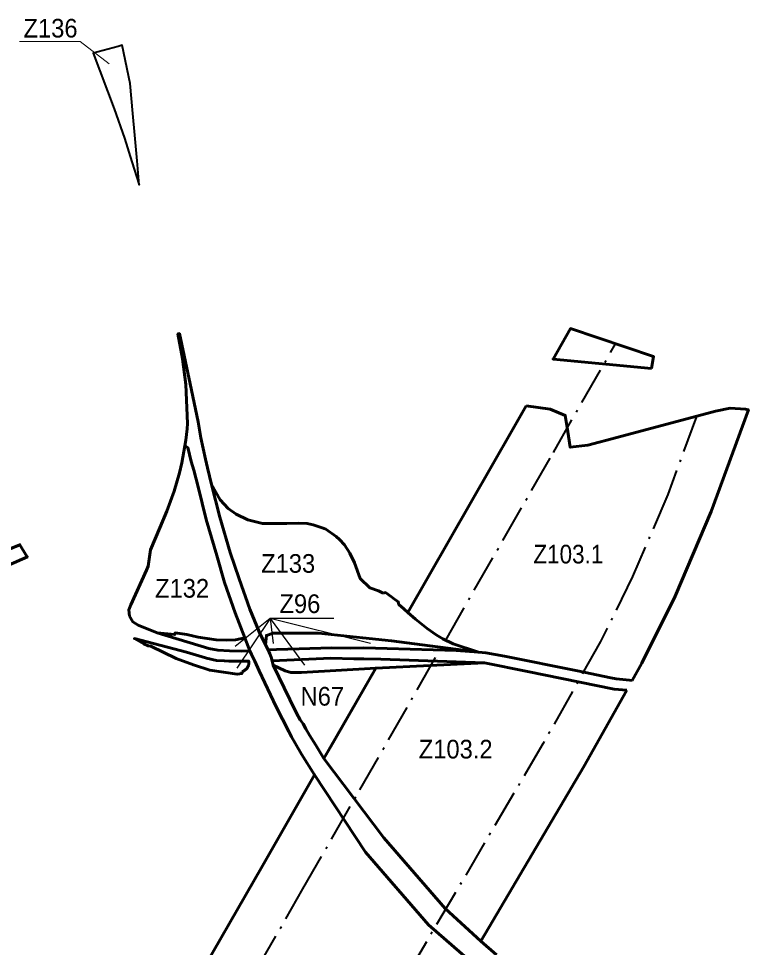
# Model space of a CAD drawing. Extents: x -650277 to -643425, y -1073980 to -1066720.
# Drawn here: x -647999 to -647061, y -1068122 to -1066928 of the extents above; entities that cross this region are included whole.
import ezdxf

# ---------------------------------------------------------------- set-up
doc = ezdxf.new("R2010")
doc.units = 0
doc.header["$LTSCALE"] = 9.6
doc.linetypes.add('DOT_DASHED', pattern=[7.7, 5, -1.2, 0.3, -1.2])
for name, color, linetype, lineweight in [('1', 7, 'Continuous', 60), ('15', 7, 'Continuous', 60), ('2', 7, 'Continuous', 40), ('42', 7, 'Continuous', 60), ('59', 7, 'Continuous', 25), ('60', 7, 'Continuous', 60), ('61', 7, 'Continuous', 60), ('62', 7, 'DOT_DASHED', 40), ('63', 7, 'Continuous', 25)]:
    doc.layers.add(name, color=color, linetype=linetype, lineweight=lineweight)

msp = doc.modelspace()

# ---------------------------------------------------------------- linework, layer by layer
at = {"layer": '1'}
for points in [[(-647708.71, -1067723.99), (-647721.05, -1067691.73), (-647734.63, -1067652.57), (-647744.61, -1067617.96), (-647758.25, -1067571.79), (-647768.5, -1067529.75), (-647773.96, -1067508.48), (-647777.55, -1067496.95), (-647781.85, -1067479.19), (-647785.64, -1067477.02), (-647789.39, -1067498.84), (-647792.54, -1067511.85), (-647799.39, -1067535.48)], [(-647704.458, -1067572.034), (-647719.661, -1067564.884), (-647729.802, -1067557.462), (-647740.124, -1067546.265), (-647751.41, -1067526.58), (-647740.49, -1067568.67), (-647727.37, -1067614.33), (-647715.92, -1067648.12), (-647702.04, -1067686.86), (-647690.09, -1067716.05), (-647681.91, -1067732.74), (-647680.804, -1067720.745), (-647672, -1067718), (-647643, -1067718), (-647614, -1067718), (-647557, -1067724), (-647520.145, -1067727.879), (-647408.2, -1067742.37)], [(-647799.39, -1067535.48), (-647808.71, -1067561.03), (-647817.59, -1067582.4)], [(-647591.227, -1067593.613), (-647604.415, -1067584.047), (-647606.559, -1067583.309), (-647620.586, -1067578.478), (-647628.441, -1067576.759), (-647640.087, -1067576.306), (-647654.743, -1067576.996), (-647685.968, -1067576.68), (-647704.458, -1067572.034)], [(-647817.59, -1067582.4), (-647829.97, -1067610.62), (-647832.8, -1067631.53), (-647835.06, -1067637.01), (-647855.24, -1067681.26), (-647857.51, -1067687.74), (-647856.9, -1067695.97)], [(-647573.605, -1067614.951), (-647580.539, -1067604.432), (-647586.864, -1067597.411), (-647591.227, -1067593.613)], [(-647530.82, -1067666.65), (-647536.83, -1067663.64), (-647547.663, -1067659.519), (-647560.187, -1067647.458), (-647567.744, -1067627.24), (-647573.605, -1067614.951)], [(-647499.095, -1067691.163), (-647503.97, -1067686.73), (-647510.6, -1067680.86), (-647511.24, -1067677.53), (-647517.74, -1067672.85), (-647520.13, -1067671.13), (-647527.76, -1067665.65), (-647530.82, -1067666.65)], [(-647856.9, -1067695.97), (-647852.3, -1067703.36), (-647845.74, -1067707.59), (-647821.02, -1067717.33)], [(-647474.13, -1067711.81), (-647489.3, -1067700.07), (-647499.095, -1067691.163)], [(-647821.02, -1067717.33), (-647798.5, -1067719.67), (-647798.17, -1067717.58), (-647783.13, -1067719.68), (-647768.53, -1067722.82), (-647745.41, -1067726.6), (-647732.71, -1067727.02), (-647720.45, -1067726.49), (-647708.71, -1067723.99)], [(-647453.87, -1067724.97), (-647462.45, -1067719.84), (-647474.13, -1067711.81)], [(-647408.2, -1067742.37), (-647440.81, -1067731.38), (-647453.87, -1067724.97)]]:
    msp.add_lwpolyline(points, dxfattribs=at)
at = {"layer": '15'}
msp.add_lwpolyline([(-647988.235, -1067619.912), (-647995.04, -1067608.56), (-647997.68, -1067604.11), (-648144.83, -1067664.48), (-648151.6, -1067668.12), (-648157.2, -1067674.32), (-648161, -1067680.96), (-648162.69, -1067684), (-648164.09, -1067686.51), (-648171.21, -1067693.37), (-648187.139, -1067699.179), (-648233.264, -1067731.288), (-648251.711, -1067741.124), (-648258.96, -1067725.37), (-648262.632, -1067726.711), (-648255.016, -1067742.886), (-648319.983, -1067777.526), (-648370.113, -1067804.22), (-648360.993, -1067821.027), (-648222.872, -1067748.412), (-648146.127, -1067695.8), (-648110.36, -1067673.133), (-647988.052, -1067619.624)], close=True, dxfattribs=at)
at = {"layer": '2'}
msp.add_lwpolyline([(-647876.57, -1067043.5), (-647863.04, -1067081.36), (-647853.65, -1067111.91), (-647844.3, -1067141.25), (-647847.09, -1067110.58), (-647850.07, -1067077.71), (-647852.63, -1067049.52), (-647856.11, -1067011.21), (-647866.14, -1066961.98), (-647871.52, -1066963.43), (-647903.5, -1066972.05), (-647903.5, -1066972.05)], close=True, dxfattribs=at)
at = {"layer": '42'}
msp.add_lwpolyline([(-647606.818, -1067879.061), (-647540.208, -1067762.876), (-647635.758, -1067768.38), (-647649.22, -1067768.38), (-647656.469, -1067766.309), (-647672.05, -1067758.98), (-647650.8, -1067803.28), (-647642.29, -1067820.76), (-647637.21, -1067829.29), (-647633.69, -1067834.31), (-647630.3, -1067841.02), (-647625.37, -1067848.86), (-647617.25, -1067861.95)], close=True, dxfattribs=at)
at = {"layer": '59', "lineweight": 13}
msp.add_lwpolyline([(-647998, -1066957), (-647920, -1066957), (-647883, -1066986)], dxfattribs=at)
at = {"layer": '60'}
for points in [[(-647606.818, -1067879.061), (-647617.25, -1067861.95), (-647625.37, -1067848.86), (-647630.3, -1067841.02), (-647633.69, -1067834.31), (-647637.21, -1067829.29), (-647642.29, -1067820.76), (-647650.8, -1067803.28), (-647672.05, -1067758.98), (-647673.47, -1067753.48), (-647673.47, -1067753.48), (-647674.67, -1067748.73), (-647676.47, -1067744.5), (-647678.66, -1067739.38), (-647681.91, -1067732.74), (-647690.09, -1067716.05), (-647702.04, -1067686.86), (-647715.92, -1067648.12), (-647727.37, -1067614.33), (-647740.49, -1067568.67), (-647751.41, -1067526.58), (-647756.55, -1067505.32), (-647759.16, -1067494.01), (-647764.89, -1067466.64), (-647768.5, -1067446.04), (-647778.78, -1067397.1), (-647792.52, -1067332.74), (-647794.54, -1067333.14), (-647788.77, -1067365.03), (-647784.55, -1067398.01), (-647782.39, -1067448.34), (-647782.5, -1067455.11), (-647784.36, -1067469.6), (-647785.64, -1067477.02), (-647781.85, -1067479.19), (-647777.55, -1067496.95), (-647773.96, -1067508.48), (-647768.5, -1067529.75), (-647758.25, -1067571.79), (-647744.61, -1067617.96), (-647734.63, -1067652.57), (-647721.05, -1067691.73), (-647708.71, -1067723.99), (-647702.21, -1067740.43), (-647699.89, -1067745.24), (-647697.85, -1067749.46), (-647695.71, -1067753.9), (-647690.19, -1067766.37), (-647668.13, -1067812.76), (-647651.94, -1067844.36), (-647648.33, -1067851.17), (-647643.83, -1067859.13), (-647635.77, -1067873.43), (-647618.773, -1067899.914)], [(-647783.54, -1067742.11), (-647850.45, -1067724.77), (-647838.18, -1067731.62), (-647832.56, -1067734.22), (-647829.49, -1067734.58), (-647796.87, -1067750.25), (-647774.54, -1067758.68), (-647753.53, -1067765.58), (-647718.54, -1067770.6), (-647712.01, -1067769.63), (-647712.26, -1067767.28)], [(-647712.26, -1067767.28), (-647711.773, -1067767.135), (-647711.286, -1067766.968), (-647710.799, -1067766.777), (-647710.315, -1067766.562), (-647709.834, -1067766.324), (-647709.359, -1067766.062), (-647708.892, -1067765.776), (-647708.433, -1067765.466), (-647707.985, -1067765.133), (-647707.55, -1067764.777), (-647707.128, -1067764.398), (-647706.723, -1067763.999), (-647706.335, -1067763.579), (-647705.966, -1067763.14), (-647705.617, -1067762.683), (-647705.29, -1067762.21), (-647704.985, -1067761.721), (-647704.704, -1067761.22), (-647704.447, -1067760.707), (-647704.216, -1067760.184), (-647704.01, -1067759.653), (-647703.83, -1067759.117), (-647703.675, -1067758.576), (-647703.547, -1067758.033), (-647703.445, -1067757.489), (-647703.368, -1067756.946), (-647703.315, -1067756.406), (-647703.287, -1067755.87), (-647703.282, -1067755.341), (-647703.3, -1067754.818), (-647703.34, -1067754.304), (-647703.4, -1067753.8), (-647711.09, -1067753.71), (-647728.98, -1067754.07), (-647734.69, -1067753.66), (-647744.74, -1067752.93), (-647757.74, -1067749.96), (-647759.13, -1067749.54), (-647783.54, -1067742.11)], [(-647405.026, -1068113.904), (-647451.024, -1068071.886), (-647530.038, -1067980.839), (-647606.818, -1067879.061)], [(-647618.773, -1067899.914), (-647553.628, -1067999.427), (-647472.338, -1068093.096), (-647419.713, -1068138.871)], [(-647385.13, -1068131.51), (-647405.026, -1068113.904)]]:
    msp.add_lwpolyline(points, dxfattribs=at)
for points in [[(-647754.88, -1067737.59), (-647743.12, -1067739.93), (-647728.29, -1067740.64), (-647713.15, -1067741), (-647702.21, -1067740.43), (-647708.71, -1067723.99), (-647720.45, -1067726.49), (-647732.71, -1067727.02), (-647745.41, -1067726.6), (-647768.53, -1067722.82), (-647783.13, -1067719.68), (-647798.17, -1067717.58), (-647798.5, -1067719.67), (-647821.02, -1067717.33)], [(-647596.91, -1067736.61), (-647572.33, -1067737.03), (-647555.58, -1067736.71), (-647525.685, -1067737.542), (-647436.72, -1067740.02), (-647408.2, -1067742.37), (-647520.145, -1067727.879), (-647557, -1067724), (-647614, -1067718), (-647643, -1067718), (-647672, -1067718), (-647680.804, -1067720.745), (-647681.91, -1067732.74), (-647678.66, -1067739.38), (-647678.66, -1067739.38), (-647667.76, -1067739.01), (-647638.75, -1067738.03)], [(-647540.208, -1067762.876), (-647400.63, -1067756.19), (-647533.597, -1067751.344), (-647555.67, -1067750.91), (-647568.36, -1067750.7), (-647597.83, -1067750.21), (-647673.47, -1067753.48), (-647672.05, -1067758.98), (-647672.05, -1067758.98), (-647656.469, -1067766.309), (-647649.22, -1067768.38), (-647635.758, -1067768.38)]]:
    msp.add_lwpolyline(points, close=True, dxfattribs=at)
at = {"layer": '61'}
msp.add_lwpolyline([(-647185.93, -1067377.38), (-647184.97, -1067372.22), (-647183.09, -1067362.16), (-647289.924, -1067326.309), (-647312.383, -1067365.484)], close=True, dxfattribs=at)
for points in [[(-647346.944, -1067425.768), (-647364.024, -1067455.561), (-647499.095, -1067691.163), (-647489.3, -1067700.07)], [(-647243.39, -1067469.81), (-647252.99, -1067472.35), (-647267.49, -1067476.23), (-647290.23, -1067478.89), (-647292.51, -1067464.56), (-647294.31, -1067453.26), (-647296.75, -1067437.91), (-647315.89, -1067429.71), (-647346.944, -1067425.768)], [(-647061.252, -1067430.908), (-647061.252, -1067430.908), (-647063.45, -1067430.19), (-647064.87, -1067429.73), (-647084.77, -1067428.64), (-647103.55, -1067432.54), (-647243.39, -1067469.81)], [(-647210.537, -1067778.594), (-647198.088, -1067756.5), (-647155.592, -1067670.17), (-647108.971, -1067561.55), (-647061.252, -1067430.908)], [(-647489.3, -1067700.07), (-647474.13, -1067711.81), (-647462.45, -1067719.84), (-647453.87, -1067724.97), (-647440.81, -1067731.38), (-647408.2, -1067742.37), (-647398.74, -1067743.15), (-647374.55, -1067747.34)], [(-647374.55, -1067747.34), (-647280.78, -1067766.44), (-647237.91, -1067775.18), (-647231.17, -1067776.55), (-647213.92, -1067778.26), (-647210.537, -1067778.594)], [(-647400.63, -1067756.19), (-647540.208, -1067762.876), (-647593.267, -1067855.425), (-647606.818, -1067879.061)], [(-647217.611, -1067791.149), (-647233.83, -1067789.69), (-647345.11, -1067767.28), (-647400.63, -1067756.19)], [(-647405.026, -1068113.904), (-647273.297, -1067889.981), (-647217.611, -1067791.149)], [(-647606.818, -1067879.061), (-647530.038, -1067980.839), (-647451.024, -1068071.886), (-647405.026, -1068113.904)], [(-647464.94, -1068215.752), (-647461.188, -1068209.373), (-647419.713, -1068138.871), (-647472.338, -1068093.096), (-647553.628, -1067999.427), (-647618.773, -1067899.914), (-647685.819, -1068016.861)], [(-647685.819, -1068016.861), (-647781.346, -1068183.485), (-647791.055, -1068200.507)]]:
    msp.add_lwpolyline(points, dxfattribs=at)
at = {"layer": '62'}
for points in [[(-647729.261, -1068213.27), (-647633.767, -1068046.703), (-647560.654, -1067919.174), (-647311.972, -1067485.403), (-647231.921, -1067345.773)], [(-647128.118, -1067439.088), (-647164.761, -1067539.408), (-647210.113, -1067645.071), (-647251.182, -1067728.502), (-647325.296, -1067860.04), (-647512.903, -1068178.95), (-647726.877, -1068542.68), (-647850.594, -1068756.441), (-647875.691, -1068807.609), (-647903.473, -1068876.174), (-647924.037, -1068940.973), (-647945.559, -1069039.601), (-647956.348, -1069145.994), (-647956.677, -1069214.977), (-647954.925, -1069248.93), (-647950.785, -1069292.731), (-647945.699, -1069329.377), (-647937.748, -1069374.683)]]:
    msp.add_lwpolyline(points, dxfattribs=at)
at = {"layer": '63'}
for q in [(-647672, -1067731), (-647632, -1067759)]:
    msp.add_line((-647676, -1067699), q, dxfattribs=at)
for points in [[(-647594, -1067699), (-647676, -1067699), (-647721, -1067735)], [(-647547, -1067731), (-647676, -1067699), (-647719, -1067763)]]:
    msp.add_lwpolyline(points, dxfattribs=at)

# ---------------------------------------------------------------- texts
at = {"layer": '59', "width": 0.95}
msp.add_text('Z136', height=24, dxfattribs=at).set_placement((-647993, -1066952))
at = {"layer": '63'}
for s, width, p in [('Z103.1', 0.9, (-647337.666, -1067628.26)), ('Z133', 0.95, (-647687.579, -1067640.215)), ('Z132', 0.95, (-647823.879, -1067672.215)), ('Z96', 0.95, (-647664, -1067692)), ('N67', 0.95, (-647636.885, -1067811.038)), ('Z103.2', 0.95, (-647485, -1067879))]:
    msp.add_text(s, height=24, dxfattribs=dict(at, width=width)).set_placement(p)

doc.saveas('drawing.dxf')
